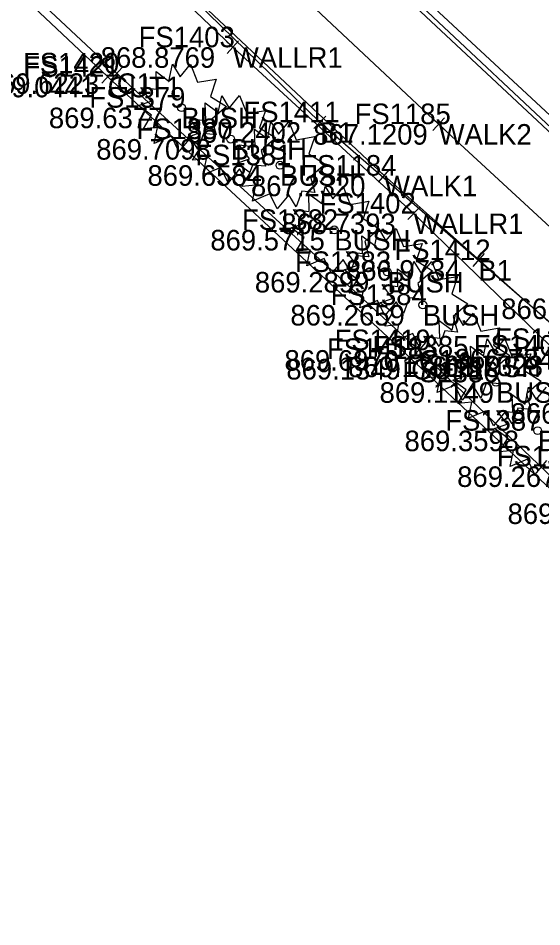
# Model space of a CAD drawing. Extents: x 1469677 to 1493262, y 375219 to 389293.
# Drawn here: x 1479711.5 to 1479742.1, y 379739.8 to 379792.9 of the extents above; entities that cross this region are included whole.
import ezdxf

# ---------------------------------------------------------------- set-up
doc = ezdxf.new("R2010")
doc.units = 0
for name, color, linetype in [('DR_X_Cells', 7, 'Continuous'), ('DV_X_Lot_Line', 7, 'Continuous'), ('DV_X_Text', 7, 'Continuous'), ('GK_Visualization', 7, 'Continuous'), ('PNTELEV', 7, 'Continuous'), ('RD_P_Text', 7, 'Continuous'), ('RW_P_Const_Limits', 7, 'Continuous'), ('RW_P_Esmt_SW', 7, 'Continuous'), ('SV_X_Mon_Cells_Found', 7, 'Continuous'), ('text', 7, 'Continuous')]:
    doc.layers.add(name, color=color, linetype=linetype)

msp = doc.modelspace()

# ---------------------------------------------------------------- linework, layer by layer
at = {"layer": 'DR_X_Cells'}
msp.add_lwpolyline([(1479756.217, 379756.165), (1479757.574, 379758.774), (1479757.809, 379760.44), (1479756.184, 379761.773), (1479753.461, 379764.221), (1479749.272, 379767.89), (1479743.159, 379773.17), (1479734.585, 379781.475), (1479724.018, 379791.188), (1479717.004, 379797.909), (1479704.341, 379809.227)], dxfattribs=at)
at = {"layer": 'DV_X_Lot_Line'}
for points in [[(1479760.141, 379765.373), (1479756.862, 379768.221), (1479747.096, 379776.511), (1479736.047, 379786.698), (1479722.324, 379799.575), (1479705.728, 379814.895), (1479685.769, 379833.709)], [(1479782.769, 379741.06), (1479767.055, 379754.294), (1479759.061, 379761.026), (1479757.309, 379762.481), (1479754.256, 379765.105), (1479744.261, 379773.561), (1479732.859, 379783.688), (1479719.35, 379796.385), (1479703.027, 379811.462), (1479682.443, 379830.686)]]:
    msp.add_lwpolyline(points, dxfattribs=at)
at = {"layer": 'PNTELEV'}
for p, q in [((1479724.386, 379790.85), (1479723.65, 379791.527)), ((1479723.68, 379790.82), (1479724.356, 379791.556)), ((1479724.018, 379791.188), (1479724.018, 379791.188)), ((1479717.067, 379789.122), (1479716.335, 379789.803)), ((1479716.361, 379789.096), (1479717.041, 379789.829)), ((1479717.598, 379789.324), (1479716.86, 379789.999)), ((1479716.891, 379789.293), (1479717.567, 379790.031)), ((1479716.701, 379789.463), (1479716.701, 379789.463)), ((1479717.229, 379789.662), (1479717.229, 379789.662)), ((1479728.749, 379787.158), (1479729.465, 379786.46)), ((1479729.456, 379787.167), (1479728.758, 379786.451)), ((1479736.415, 379786.359), (1479735.679, 379787.037)), ((1479735.708, 379786.33), (1479736.386, 379787.066)), ((1479729.107, 379786.809), (1479729.107, 379786.809)), ((1479736.047, 379786.698), (1479736.047, 379786.698)), ((1479733.233, 379783.356), (1479732.485, 379784.02)), ((1479732.527, 379783.314), (1479733.191, 379784.062)), ((1479732.859, 379783.688), (1479732.859, 379783.688)), ((1479734.944, 379781.128), (1479734.226, 379781.823)), ((1479734.237, 379781.116), (1479734.933, 379781.835)), ((1479734.585, 379781.475), (1479734.585, 379781.475)), ((1479737.998, 379779.082), (1479738.752, 379778.426)), ((1479738.703, 379779.131), (1479738.047, 379778.376)), ((1479738.375, 379778.754), (1479738.375, 379778.754)), ((1479735.256, 379773.148), (1479734.534, 379773.839)), ((1479734.55, 379773.132), (1479735.24, 379773.855)), ((1479734.812, 379772.635), (1479734.082, 379773.318)), ((1479734.106, 379772.611), (1479734.788, 379773.342)), ((1479734.895, 379773.493), (1479734.895, 379773.493)), ((1479734.447, 379772.976), (1479734.447, 379772.976))]:
    msp.add_line(p, q, dxfattribs=at)
at = {"layer": 'RD_P_Text'}
for points in [[(1479752.341, 379756.82), (1479734.895, 379773.493), (1479717.229, 379789.662), (1479699.298, 379806.402), (1479688.16, 379794.934), (1479685.526, 379793.897), (1479682.733, 379795.157), (1479681.263, 379797.549), (1479682.493, 379800.746), (1479693.462, 379811.911), (1479675.554, 379828.75), (1479655.832, 379847.057), (1479640.191, 379861.809), (1479628.558, 379849), (1479624.614, 379847.664), (1479622.46, 379848.585), (1479618.996, 379850.857), (1479611.825, 379854.437), (1479601.319, 379856.892), (1479590.521, 379858.039)], [(1479751.933, 379756.629), (1479734.447, 379772.976), (1479716.701, 379789.463), (1479699.4, 379805.742), (1479688.561, 379794.786), (1479685.717, 379793.294), (1479682.291, 379794.8), (1479680.73, 379797.254), (1479682.169, 379801.19), (1479692.652, 379811.907), (1479675.183, 379828.391), (1479655.51, 379846.682), (1479640.151, 379860.926), (1479629.134, 379848.869), (1479624.571, 379847.215), (1479622.228, 379847.911), (1479618.757, 379850.398), (1479611.519, 379853.97), (1479601.347, 379856.369), (1479590.364, 379857.442)], [(1479695.384, 379831.416), (1479709.512, 379818.131), (1479724.003, 379804.728), (1479730.662, 379798.272), (1479750.68, 379779.69), (1479759.253, 379771.893), (1479760.555, 379770.78), (1479775.03, 379758.526)], [(1479695.135, 379830.979), (1479709.331, 379817.708), (1479723.729, 379804.193), (1479729.719, 379798.6), (1479748.963, 379780.548), (1479759.065, 379771.485), (1479760.185, 379770.473), (1479774.837, 379758.13)]]:
    msp.add_lwpolyline(points, dxfattribs=at)
at = {"layer": 'RW_P_Const_Limits'}
for points in [[(1479720.933, 379789.469), (1479721.538, 379790.204), (1479721.953, 379789.151), (1479723.045, 379789.331), (1479722.706, 379788.319), (1479723.651, 379787.724), (1479722.795, 379786.989), (1479723.045, 379786.076), (1479722.291, 379786.144), (1479721.966, 379785.231), (1479721.538, 379785.922), (1479720.86, 379785.106), (1479720.431, 379785.992), (1479719.411, 379785.562), (1479719.603, 379786.504), (1479718.791, 379786.421), (1479719.265, 379787.211), (1479718.496, 379787.779), (1479719.235, 379788.042), (1479718.628, 379788.846), (1479719.56, 379788.736), (1479719.53, 379789.774), (1479720.283, 379789.206), (1479720.49, 379790.191), (1479720.933, 379789.469)], [(1479723.806, 379787.633), (1479724.411, 379788.368), (1479724.826, 379787.315), (1479725.918, 379787.495), (1479725.579, 379786.483), (1479726.524, 379785.888), (1479725.668, 379785.153), (1479725.918, 379784.24), (1479725.164, 379784.308), (1479724.839, 379783.395), (1479724.411, 379784.087), (1479723.733, 379783.27), (1479723.304, 379784.157), (1479722.284, 379783.727), (1479722.476, 379784.668), (1479721.664, 379784.585), (1479722.138, 379785.375), (1479721.369, 379785.943), (1479722.108, 379786.207), (1479721.501, 379787.01), (1479722.433, 379786.9), (1479722.403, 379787.938), (1479723.156, 379787.37), (1479723.363, 379788.355), (1479723.806, 379787.633)], [(1479726.688, 379786.105), (1479727.293, 379786.84), (1479727.708, 379785.787), (1479728.8, 379785.967), (1479728.461, 379784.955), (1479729.406, 379784.36), (1479728.55, 379783.625), (1479728.8, 379782.712), (1479728.046, 379782.78), (1479727.721, 379781.867), (1479727.293, 379782.558), (1479726.615, 379781.742), (1479726.186, 379782.628), (1479725.166, 379782.198), (1479725.358, 379783.14), (1479724.546, 379783.057), (1479725.02, 379783.847), (1479724.251, 379784.415), (1479724.99, 379784.678), (1479724.383, 379785.482), (1479725.315, 379785.372), (1479725.285, 379786.41), (1479726.038, 379785.842), (1479726.245, 379786.827), (1479726.688, 379786.105)], [(1479729.86, 379782.327), (1479730.465, 379783.062), (1479730.88, 379782.009), (1479731.972, 379782.189), (1479731.633, 379781.177), (1479732.578, 379780.582), (1479731.722, 379779.847), (1479731.972, 379778.934), (1479731.218, 379779.002), (1479730.893, 379778.089), (1479730.465, 379778.78), (1479729.787, 379777.964), (1479729.358, 379778.85), (1479728.338, 379778.42), (1479728.53, 379779.362), (1479727.718, 379779.279), (1479728.192, 379780.069), (1479727.423, 379780.637), (1479728.162, 379780.9), (1479727.555, 379781.704), (1479728.487, 379781.594), (1479728.457, 379782.632), (1479729.21, 379782.064), (1479729.417, 379783.049), (1479729.86, 379782.327)], [(1479732.965, 379779.87), (1479733.57, 379780.605), (1479733.985, 379779.552), (1479735.077, 379779.732), (1479734.738, 379778.72), (1479735.683, 379778.125), (1479734.827, 379777.39), (1479735.077, 379776.477), (1479734.323, 379776.545), (1479733.998, 379775.632), (1479733.57, 379776.324), (1479732.892, 379775.507), (1479732.463, 379776.394), (1479731.443, 379775.964), (1479731.635, 379776.905), (1479730.823, 379776.822), (1479731.297, 379777.612), (1479730.528, 379778.18), (1479731.267, 379778.444), (1479730.66, 379779.247), (1479731.592, 379779.137), (1479731.562, 379780.175), (1479732.315, 379779.607), (1479732.522, 379780.592), (1479732.965, 379779.87)], [(1479735.041, 379777.941), (1479735.646, 379778.676), (1479736.061, 379777.623), (1479737.153, 379777.803), (1479736.814, 379776.791), (1479737.759, 379776.196), (1479736.903, 379775.461), (1479737.153, 379774.548), (1479736.399, 379774.616), (1479736.074, 379773.703), (1479735.646, 379774.395), (1479734.968, 379773.578), (1479734.539, 379774.465), (1479733.519, 379774.035), (1479733.711, 379774.976), (1479732.899, 379774.893), (1479733.373, 379775.683), (1479732.604, 379776.251), (1479733.343, 379776.515), (1479732.736, 379777.318), (1479733.668, 379777.208), (1479733.638, 379778.246), (1479734.391, 379777.678), (1479734.598, 379778.663), (1479735.041, 379777.941)], [(1479737.486, 379774.926), (1479738.091, 379775.661), (1479738.506, 379774.608), (1479739.598, 379774.788), (1479739.259, 379773.776), (1479740.204, 379773.181), (1479739.348, 379772.446), (1479739.598, 379771.533), (1479738.844, 379771.601), (1479738.519, 379770.688), (1479738.091, 379771.379), (1479737.413, 379770.563), (1479736.984, 379771.449), (1479735.964, 379771.019), (1479736.156, 379771.961), (1479735.344, 379771.878), (1479735.818, 379772.668), (1479735.049, 379773.236), (1479735.788, 379773.499), (1479735.181, 379774.303), (1479736.113, 379774.193), (1479736.083, 379775.231), (1479736.836, 379774.663), (1479737.043, 379775.648), (1479737.486, 379774.926)], [(1479739.318, 379773.424), (1479739.923, 379774.159), (1479740.338, 379773.106), (1479741.43, 379773.286), (1479741.091, 379772.274), (1479742.036, 379771.679), (1479741.18, 379770.944), (1479741.43, 379770.031), (1479740.676, 379770.099), (1479740.351, 379769.186), (1479739.923, 379769.877), (1479739.245, 379769.061), (1479738.816, 379769.947), (1479737.796, 379769.517), (1479737.988, 379770.459), (1479737.176, 379770.376), (1479737.65, 379771.166), (1479736.881, 379771.734), (1479737.62, 379771.997), (1479737.013, 379772.801), (1479737.945, 379772.691), (1479737.915, 379773.729), (1479738.668, 379773.161), (1479738.875, 379774.146), (1479739.318, 379773.424)], [(1479742.357, 379767.052), (1479741.679, 379766.235), (1479741.25, 379767.122), (1479740.23, 379766.692), (1479740.422, 379767.634), (1479739.61, 379767.55), (1479740.084, 379768.34), (1479739.315, 379768.909), (1479740.054, 379769.172), (1479739.447, 379769.975), (1479740.379, 379769.865), (1479740.349, 379770.904), (1479741.102, 379770.335), (1479741.309, 379771.32), (1479741.752, 379770.599)], [(1479741.752, 379770.599), (1479742.357, 379771.334)]]:
    msp.add_lwpolyline(points, dxfattribs=at)
for centre in [(1479721.017, 379787.66), (1479723.89, 379785.824), (1479726.772, 379784.296), (1479729.944, 379780.517), (1479733.049, 379778.061), (1479735.125, 379776.132), (1479737.57, 379773.116), (1479739.402, 379771.614), (1479741.836, 379768.789)]:
    msp.add_circle(centre, 0.23, dxfattribs=at)
at = {"layer": 'SV_X_Mon_Cells_Found'}
msp.add_lwpolyline([(1477164.629, 382297.849), (1479615.888, 379904.59), (1480413.414, 379159.216)], dxfattribs=at)
at = {"layer": 'text'}
msp.add_lwpolyline([(1479700.791, 379810.474), (1479703.421, 379811.158), (1479704.398, 379810.048), (1479708.429, 379806.714), (1479717.526, 379798.095), (1479729.107, 379786.809), (1479738.375, 379778.754), (1479747.99, 379770.392), (1479758.225, 379761.837), (1479757.039, 379755.523)], dxfattribs=at)

# ---------------------------------------------------------------- texts
at = {"layer": 'DV_X_Text'}
for s, p in [('868.8769', (1479716.289, 379789.988)), ('869.0441', (1479709.282, 379788.263)), ('869.6223', (1479709.51, 379788.462)), ('869.6377', (1479713.261, 379786.459)), ('867.2402', (1479721.312, 379785.609)), ('867.1209', (1479728.716, 379785.498)), ('869.7098', (1479716.03, 379784.623)), ('869.6584', (1479719.025, 379783.095)), ('867.2320', (1479725.074, 379782.488)), ('868.7393', (1479726.847, 379780.275)), ('869.5715', (1479722.699, 379779.317)), ('866.9734', (1479730.627, 379777.554)), ('869.2899', (1479725.302, 379776.86)), ('866.8160', (1479739.708, 379775.311)), ('869.2659', (1479727.378, 379774.931)), ('869.6970', (1479727.034, 379772.293)), ('866.7841', (1479736.984, 379772.361)), ('869.1349', (1479727.144, 379771.776)), ('869.1761', (1479730.757, 379771.916)), ('868.7328', (1479735.449, 379771.97)), ('869.1149', (1479732.592, 379770.414)), ('866.6285', (1479740.252, 379769.192)), ('869.3598', (1479734.052, 379767.589)), ('869.2679', (1479737.129, 379765.5)), ('869.4481', (1479740.075, 379763.336))]:
    msp.add_text(s, height=1.2, dxfattribs=at).set_placement(p)
at = {"layer": 'GK_Visualization'}
for s, p in [('WALLR1', (1479724.018, 379789.988)), ('GUT1', (1479716.701, 379788.263)), ('C1', (1479717.229, 379788.462)), ('BUSH', (1479721.018, 379786.459)), ('B1', (1479729.107, 379785.609)), ('WALK2', (1479736.047, 379785.498)), ('BUSH', (1479723.891, 379784.623)), ('BUSH', (1479726.773, 379783.095)), ('WALK1', (1479732.859, 379782.488)), ('WALLR1', (1479734.585, 379780.275)), ('BUSH', (1479729.945, 379779.317)), ('B1', (1479738.375, 379777.554)), ('BUSH', (1479733.05, 379776.86)), ('BUSH', (1479735.126, 379774.931)), ('C1', (1479734.895, 379772.293)), ('GUT1', (1479734.447, 379771.776)), ('BUSH', (1479737.571, 379771.916)), ('BUSH', (1479739.403, 379770.414)), ('BUSH', (1479741.837, 379767.589))]:
    msp.add_text(s, height=1.2, dxfattribs=at).set_placement(p)
at = {"layer": 'RW_P_Esmt_SW'}
for s, p in [('FS1403', (1479718.51, 379791.188)), ('FS1420', (1479711.75, 379789.662)), ('FS1421', (1479711.777, 379789.463)), ('FS1379', (1479715.624, 379787.659)), ('FS1411', (1479724.637, 379786.809)), ('FS1185', (1479731.135, 379786.698)), ('FS1380', (1479718.383, 379785.823)), ('FS1381', (1479721.821, 379784.295)), ('FS1184', (1479727.957, 379783.688)), ('FS1402', (1479729.087, 379781.475)), ('FS1382', (1479724.551, 379780.517)), ('FS1412', (1479733.463, 379778.754)), ('FS1383', (1479727.646, 379778.06)), ('FS1384', (1479729.732, 379776.131)), ('FS1419', (1479729.964, 379773.493)), ('FS1385', (1479732.167, 379773.116)), ('FS1401', (1479738.103, 379773.17)), ('FS1183', (1479739.349, 379773.561)), ('FS1418', (1479729.516, 379772.976)), ('FS1386', (1479733.924, 379771.614)), ('FS1387', (1479736.433, 379768.789)), ('FS1388', (1479739.445, 379766.7))]:
    msp.add_text(s, height=1.2, dxfattribs=at).set_placement(p)

doc.saveas('drawing.dxf')
